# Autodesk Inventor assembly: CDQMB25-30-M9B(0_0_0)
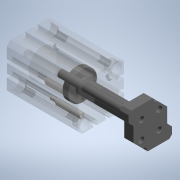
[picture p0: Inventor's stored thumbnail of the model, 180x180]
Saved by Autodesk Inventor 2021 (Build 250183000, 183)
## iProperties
Part Number: CDQMB25-30-M9B(0_0_0)
Catalog Web Link: www.cadenas.de
Description: CQM/CDQM-Compact Cylinder Guide Rod Type
Document SubType Name: Assembly
Designer: partserver
Mass: 83.8507 g
Surface Area: 351.278 cm^2
Volume: 83.8507 cm^3
Density: 1 g/cm^3
Category: PARTsolutions
PSOL_IDENT_0: {$CADENAS_DATA\23d-libs\smc_jp\actuator\compact_cylinder\cqm\cqm_asmtab.prj},262 {VTYP=3D},{STYP=ASS
PSOL_IDENT_1: TAB},{NB=CDQMB25-30-M9B(0_0_0)},{LINA=CDQMB25-30-M9B},{NN=CQM/CDQM},{DATE=09.12.2020 02:52:30},{GEOM
PSOL_IDENT_2: DATE=26.03.2020 06:55:43},{VERSION=},{LINEID=40},{WBVAR=MAGNET,THREAD1,AUTOSWITCH,LEAD,NUMBER,STROKE
PSOL_IDENT_3: ,POS,STOP,THREAD2},{WBNUMERIC=STROKE,POS}  {NB=CDQMB25-30-M9B(0_0_0)},{LINA=CDQMB25-30-M9B},{KT=DUMM
PSOL_IDENT_4: Y},{BORE=25},{TIF=A},{MOUNT=(B) Through-hole/Both ends tapped (Standard)},{MOUNTX=B},{MAGNET=D},{THR
PSOL_IDENT_5: EAD1=},{THREAD1X='','(-) M thread'},{AUTOSWITCH=-M9B},{AUTOSWITCHX='','(-) Without autoswitch','-M9N
PSOL_IDENT_6: V','M9NV', '-M9PV', 'M9PV', '-M9BV', 'M9BV','-M9NWV', 'M9NWV', '-M9PWV', 'M9PWV', '-M9BWV', 'M9BWV',
PSOL_IDENT_7: '-A96V', 'A96V', '-A93V', 'A93V', '-A90V', 'A90V', '-M9N', 'M9N', '-M9P', 'M9P', '-M9B', 'M9B', '-M
PSOL_IDENT_8: 9NW', 'M9NW', '-M9PW', 'M9PW', '-M9BW', 'M9BW', '-A96', 'A96','-A93', 'A93', '-A90', 'A90', '-M9NAV'
PSOL_IDENT_9: , 'M9NAV', '-M9PAV', 'M9PAV', '-M9BAV', 'M9BAV', '-M9NA', 'M9NA', '-M9PA','M9PA', '-M9BA', 'M9BA'},{
PSOL_IDENT_10: LEAD=},{LEADX='','(-) 0.5 m', 'M','(M) 1 m' , 'L','(L) 3 m' , 'Z','(Z) 5 m' },{NUMBER=},{NUMBERX='',
PSOL_IDENT_11: '(-) 2 pcs', 'S', '(S) 1 pc'},{STROKE=30},{STROKEX=[15:50/5]},{POS=0},{SMAX=50},{SMINX=15},{SMIN=15
PSOL_IDENT_12: },{STOP=0},{COM=-},{THREAD2=0},{ORDER=CDQMB25-30-M9B},{A=45.5},{A1=35.5},{A2=45.5},{B=32.5},{B1=22.5
PSOL_IDENT_13: },{B2=32.5},{EA=40},{EB=38},{EC=0.0},{F=5.5},{F1=5.5},{HA=M5x0.8},{OA=M6x1.0},{HB=5 +0.2/0},{IA=52},
PSOL_IDENT_14: {IB=50.5},{J=0.0},{KA=22 +0.1/-0.1},{KB=15.6},{L=5.0},{M=28.0},{N=5.4},{OB=9.0},{Q=11.0},{Q1=11.0},{
PSOL_IDENT_15: RA=10},{RB=7.0},{T=1.0},{V=30.0},{W=8},{Z=0},{PP=M5x0.8},{PTN=-},{PTF=-},{P=M5x0.8},{PPATH=assembly/
PSOL_IDENT_16: cqm_asmsbl.prj},{MODEL=CDQMB25-30-M9B},{NENN=CDQMB25}
NB: CDQMB25-30-M9B(0_0_0)
NN: CQM/CDQM
NT: Compact Cylinder Guide Rod Type
NBSYN: $ORDER.($POS._$STOP._$THREAD2.)
LINA: CDQMB25-30-M9B
CATALOG: SMC (JP
ROWDESC: CDQMB25
BORE: 25
MOUNT: (B) Through-hole/Both ends tapped (Standard)
MAGNET: (D) With magnet
THREAD1: (-) M thread
AUTOSWITCH: M9B Solid state-General-Grommet-Indicator light:Yes-2 wire-In line
LEAD: (-) 0.5 m
NUMBER: (-) 2 pcs
STROKE: 30
POS: 0
STOP: Standard stroke
COM: -
THREAD2: on
ARTICLENO: CDQMB25-30-M9B(0_0_0)
BOMINFO: CDQMB25-30-M9B
CREATOR: CADENAS GmbH
Title: CDQMB25-30-M9B
Author: Cadenas PARTsolutions
Comments: Compact Cylinder Guide Rod Type
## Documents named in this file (4)
- D:\01 Paralaia\Grupos de Traballo\GT Maquetas\CAD 3D\E_AlimentaciónV1\SMC_JP_CDQMB2530M9B000\CDQMB25-30-M9B(0_0_0).iam
- D:\01 Paralaia\Grupos de Traballo\GT Maquetas\CAD 3D\E_AlimentaciónV1\SMC_JP_CDQMB2530M9B000\CDQMB25-30-M9B(0)_BODY.ipt
- D:\01 Paralaia\Grupos de Traballo\GT Maquetas\CAD 3D\E_AlimentaciónV1\SMC_JP_CDQMB2530M9B000\CDQMB25-30(0)_ROD.ipt
- D:\01 Paralaia\Grupos de Traballo\GT Maquetas\CAD 3D\E_AlimentaciónV1\SMC_JP_CDQMB2530M9B000\CQM-M9B.ipt
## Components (4 placed, 3 different names)
1. CDQMB25-30-M9B(0)_BODY:1 — Insertar:1, Coincidencia:1
2. CDQMB25-30(0)_ROD:1 — Insertar:1, Coincidencia:1
3. CQM-M9B:1
4. CQM-M9B:2
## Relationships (2: Insert 1, Mate 1)
- Insertar:1: CDQMB25-30-M9B(0)_BODY:1 ↔ CDQMB25-30(0)_ROD:1
- Coincidencia:1 [Mate]: CDQMB25-30-M9B(0)_BODY:1 ↔ CDQMB25-30(0)_ROD:1
